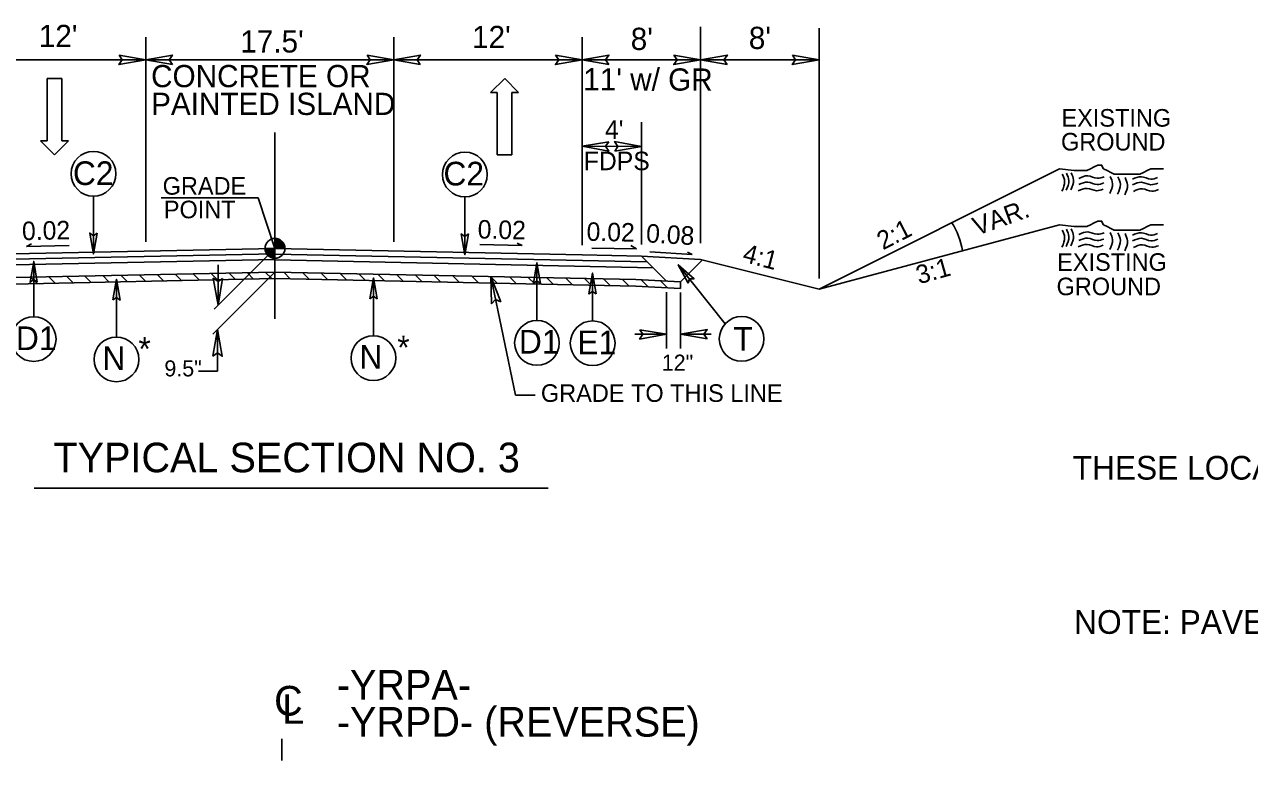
# Model space of a CAD drawing. Extents: x 573813 to 575363, y -54752 to -53123.
# Drawn here: x 574834.1 to 574928.2, y -53497.7 to -53441.2 of the extents above; entities that cross this region are included whole.
import ezdxf

# ---------------------------------------------------------------- set-up
doc = ezdxf.new("R2010")
doc.units = 0
for name, color, linetype in [('Old_Level_1', 7, 'Continuous'), ('Old_Level_11', 7, 'Continuous'), ('Old_Level_2', 7, 'Continuous'), ('Old_Level_3', 7, 'Continuous'), ('Prop Lane Arrow CELL', 7, 'Continuous'), ('Prop Pavement Schedule Description CELL', 7, 'Continuous'), ('Typical Grade Point Symbol CELL', 7, 'Continuous'), ('Typical ID Circle CELL', 7, 'Continuous'), ('Typical Terminator CELL', 7, 'Continuous'), ('Typical Text ID Circle CELL', 7, 'Continuous')]:
    doc.layers.add(name, color=color, linetype=linetype)

msp = doc.modelspace()

# ---------------------------------------------------------------- linework, layer by layer
at = {"layer": 'Old_Level_1'}
for p, q in [((574895.117, -53461.543), (574913.593, -53452.305)), ((574895.117, -53461.543), (574913.593, -53456.608)), ((574853.333, -53458.418), (574829.741, -53458.908)), ((574834.258, -53458.269), (574834.638, -53458.079)), ((574837.528, -53458.201), (574834.258, -53458.269)), ((574853.333, -53458.418), (574876.925, -53458.908)), ((574869.063, -53458.13), (574872.325, -53458.198)), ((574872.325, -53458.198), (574871.946, -53458.009)), ((574853.333, -53459.272), (574824.319, -53459.876)), ((574853.333, -53458.826), (574824.775, -53459.42)), ((574853.333, -53458.863), (574881.928, -53459.458)), ((574853.333, -53459.302), (574882.376, -53459.906)), ((574876.925, -53458.908), (574881.473, -53459.003)), ((574881.473, -53459.003), (574883.405, -53460.936)), ((574886.021, -53459.269), (574881.473, -53459.003)), ((574886.168, -53459.306), (574884.483, -53460.992)), ((574886.021, -53459.269), (574895.117, -53461.543)), ((574853.333, -53460.237), (574825.608, -53460.814)), ((574838.737, -53460.541), (574839.227, -53461.03)), ((574840.122, -53460.512), (574840.612, -53461.002)), ((574841.508, -53460.483), (574841.998, -53460.973)), ((574842.893, -53460.454), (574843.383, -53460.944)), ((574844.279, -53460.425), (574844.768, -53460.915)), ((574845.664, -53460.397), (574846.154, -53460.886)), ((574847.049, -53460.368), (574847.539, -53460.858)), ((574848.435, -53460.339), (574848.925, -53460.829)), ((574849.82, -53460.31), (574850.31, -53460.8)), ((574851.206, -53460.281), (574851.695, -53460.771)), ((574852.591, -53460.253), (574853.081, -53460.742)), ((574853.333, -53460.237), (574881.057, -53460.814)), ((574854.004, -53460.251), (574854.514, -53460.762)), ((574855.448, -53460.281), (574855.959, -53460.792)), ((574856.892, -53460.311), (574857.403, -53460.822)), ((574858.337, -53460.341), (574858.847, -53460.852)), ((574859.781, -53460.371), (574860.291, -53460.882)), ((574861.225, -53460.401), (574861.736, -53460.912)), ((574862.669, -53460.431), (574863.18, -53460.942)), ((574864.114, -53460.461), (574864.624, -53460.972)), ((574865.558, -53460.491), (574866.069, -53461.002)), ((574867.002, -53460.521), (574867.513, -53461.032)), ((574853.333, -53460.737), (574825.625, -53461.313)), ((574834.581, -53460.627), (574835.071, -53461.117)), ((574835.966, -53460.598), (574836.456, -53461.088)), ((574837.351, -53460.569), (574837.841, -53461.059)), ((574853.333, -53460.737), (574881.039, -53461.314)), ((574868.446, -53460.552), (574868.957, -53461.062)), ((574869.891, -53460.582), (574870.401, -53461.092)), ((574871.335, -53460.612), (574871.846, -53461.122)), ((574872.779, -53460.642), (574873.29, -53461.152)), ((574874.223, -53460.672), (574874.734, -53461.182)), ((574875.668, -53460.702), (574876.178, -53461.212)), ((574877.112, -53460.732), (574877.623, -53461.243)), ((574878.556, -53460.762), (574879.067, -53461.273)), ((574880, -53460.792), (574880.511, -53461.303)), ((574884.483, -53461.492), (574881.039, -53461.314)), ((574884.483, -53460.992), (574881.057, -53460.814)), ((574881.457, -53460.835), (574881.985, -53461.363)), ((574882.949, -53460.912), (574883.477, -53461.44)), ((574884.441, -53460.989), (574884.483, -53461.032)), ((574884.483, -53460.992), (574884.483, -53461.492))]:
    msp.add_line(p, q, dxfattribs=at)
for points in [[(574913.593, -53452.305), (574914.713, -53452.445), (574914.993, -53452.445), (574915.414, -53452.445), (574915.694, -53452.445), (574915.974, -53452.306), (574916.255, -53452.165), (574916.535, -53452.024), (574916.815, -53452.024), (574916.956, -53452.305), (574917.236, -53452.445), (574917.516, -53452.585), (574917.796, -53452.725), (574918.076, -53452.725), (574918.357, -53452.725), (574918.637, -53452.725), (574918.917, -53452.725), (574919.197, -53452.725), (574919.477, -53452.725), (574919.757, -53452.725), (574920.038, -53452.585), (574920.318, -53452.445), (574920.598, -53452.305), (574921.018, -53452.305), (574921.299, -53452.305), (574921.579, -53452.305)], [(574913.593, -53456.608), (574914.713, -53456.747), (574914.993, -53456.747), (574915.414, -53456.747), (574915.694, -53456.747), (574915.974, -53456.608), (574916.255, -53456.467), (574916.535, -53456.326), (574916.815, -53456.326), (574916.956, -53456.607), (574917.236, -53456.747), (574917.516, -53456.888), (574917.796, -53457.027), (574918.076, -53457.027), (574918.357, -53457.027), (574918.637, -53457.027), (574918.917, -53457.027), (574919.197, -53457.027), (574919.477, -53457.027), (574919.757, -53457.027), (574920.038, -53456.888), (574920.318, -53456.747), (574920.598, -53456.607), (574921.018, -53456.608), (574921.299, -53456.608), (574921.579, -53456.607)]]:
    msp.add_lwpolyline(points, dxfattribs=at)
at = {"layer": 'Old_Level_11'}
for p, q in [((574886.021, -53458.02), (574886.021, -53441.414)), ((574895.134, -53460.736), (574895.135, -53441.498)), ((574843.407, -53457.908), (574843.407, -53442.205)), ((574862.451, -53457.908), (574862.451, -53442.205)), ((574876.925, -53458.18), (574876.925, -53442.205)), ((574843.407, -53443.942), (574829.763, -53443.942)), ((574853.333, -53443.942), (574843.407, -53443.942)), ((574857.903, -53443.942), (574853.333, -53443.942)), ((574862.451, -53443.942), (574857.903, -53443.942)), ((574876.925, -53443.942), (574862.451, -53443.942)), ((574876.925, -53443.942), (574886.021, -53443.942)), ((574886.021, -53443.942), (574895.117, -53443.943)), ((574881.473, -53458.116), (574881.473, -53448.736)), ((574876.925, -53450.581), (574881.473, -53450.587)), ((574844.597, -53454.544), (574852.032, -53454.545)), ((574853.333, -53458.418), (574852.032, -53454.545)), ((574853.333, -53458.418), (574848.662, -53463.088)), ((574853.333, -53460.237), (574848.559, -53465.01)), ((574848.962, -53462.765), (574848.962, -53459.69)), ((574871.812, -53469.697), (574869.905, -53460.582)), ((574883.392, -53466.094), (574883.391, -53461.777)), ((574884.469, -53466.094), (574884.469, -53461.801)), ((574848.925, -53467.857), (574848.925, -53464.645)), ((574883.392, -53465.013), (574880.96, -53465.016)), ((574886.828, -53465.008), (574884.469, -53465.011)), ((574847.455, -53467.857), (574848.925, -53467.857)), ((574873.325, -53469.697), (574871.812, -53469.697)), ((574834.842, -53476.822), (574874.322, -53476.823))]:
    msp.add_line(p, q, dxfattribs=at)
for points in [[(574841.36, -53443.59), (574843.407, -53443.942), (574841.349, -53444.306), (574841.61, -53443.942)], [(574845.453, -53444.295), (574843.407, -53443.942), (574845.465, -53443.579), (574845.203, -53443.942)], [(574860.405, -53443.59), (574862.451, -53443.942), (574860.393, -53444.306), (574860.655, -53443.942)], [(574864.498, -53444.295), (574862.451, -53443.942), (574864.509, -53443.578), (574864.248, -53443.942)], [(574874.879, -53443.59), (574876.925, -53443.942), (574874.867, -53444.306), (574875.128, -53443.942)], [(574878.971, -53444.295), (574876.925, -53443.942), (574878.983, -53443.578), (574878.721, -53443.942)], [(574883.974, -53443.59), (574886.021, -53443.942), (574883.963, -53444.306), (574884.224, -53443.942)], [(574888.067, -53444.295), (574886.021, -53443.942), (574888.079, -53443.579), (574887.817, -53443.942)], [(574893.07, -53443.59), (574895.117, -53443.943), (574893.059, -53444.306), (574893.32, -53443.943)], [(574878.971, -53450.228), (574876.925, -53450.581), (574878.983, -53450.944), (574878.721, -53450.581)], [(574879.426, -53450.94), (574881.473, -53450.587), (574879.415, -53450.223), (574879.676, -53450.587)], [(574849.315, -53460.719), (574848.962, -53462.765), (574848.598, -53460.707), (574848.962, -53460.969)], [(574870.67, -53462.512), (574869.905, -53460.582), (574869.972, -53462.671), (574870.274, -53462.34)], [(574848.572, -53466.691), (574848.925, -53464.645), (574849.289, -53466.703), (574848.925, -53466.441)], [(574881.345, -53464.66), (574883.392, -53465.013), (574881.334, -53465.377), (574881.595, -53465.013)], [(574886.516, -53465.364), (574884.469, -53465.011), (574886.527, -53464.648), (574886.266, -53465.011)]]:
    msp.add_lwpolyline(points, close=True, dxfattribs=at)
msp.add_arc((574901.035, -53459.32), 5.147, 8.03481, 33.91244, dxfattribs=at)
at = {"layer": 'Old_Level_2'}
for p, q in [((574853.333, -53463.837), (574853.333, -53449.515)), ((574881.1, -53458.46), (574877.667, -53458.392)), ((574881.1, -53458.46), (574880.669, -53458.2)), ((574882.136, -53458.686), (574885.386, -53458.88)), ((574885.386, -53458.88), (574885.004, -53458.699)), ((574853.873, -53497.74), (574853.873, -53496.072))]:
    msp.add_line(p, q, dxfattribs=at)
for points in [[(574913.788, -53452.708), (574913.98, -53453.272), (574913.773, -53454.021)], [(574913.788, -53452.708), (574913.98, -53453.272), (574913.773, -53454.021)], [(574914.12, -53452.643), (574914.31, -53453.209), (574914.103, -53453.959)], [(574914.12, -53452.643), (574914.31, -53453.209), (574914.103, -53453.959)], [(574914.474, -53452.606), (574914.668, -53453.172), (574914.46, -53453.919)], [(574914.474, -53452.606), (574914.668, -53453.172), (574914.46, -53453.919)], [(574915.078, -53453.047), (574915.76, -53452.85), (574916.486, -53453.034), (574917.004, -53452.917)], [(574917.47, -53452.885), (574917.66, -53453.449), (574917.456, -53454.198)], [(574917.47, -53452.885), (574917.66, -53453.449), (574917.456, -53454.198)], [(574918.066, -53452.931), (574918.258, -53453.497), (574918.052, -53454.246)], [(574918.066, -53452.931), (574918.258, -53453.497), (574918.052, -53454.246)], [(574918.618, -53452.981), (574918.81, -53453.547), (574918.602, -53454.294)], [(574918.618, -53452.981), (574918.81, -53453.547), (574918.602, -53454.294)], [(574919.183, -53453.111), (574919.869, -53452.916), (574920.589, -53453.101), (574921.111, -53452.985)], [(574915.021, -53454.003), (574915.705, -53453.81), (574916.431, -53453.99), (574916.951, -53453.875)], [(574915.021, -53454.003), (574915.705, -53453.81), (574916.431, -53453.99), (574916.951, -53453.875)], [(574915.074, -53453.522), (574915.76, -53453.329), (574916.48, -53453.513), (574917, -53453.396)], [(574915.074, -53453.522), (574915.76, -53453.329), (574916.48, -53453.513), (574917, -53453.396)], [(574919.201, -53453.54), (574919.887, -53453.343), (574920.607, -53453.53), (574921.13, -53453.413)], [(574919.201, -53453.54), (574919.887, -53453.343), (574920.607, -53453.53), (574921.13, -53453.413)], [(574919.271, -53454.037), (574919.955, -53453.841), (574920.679, -53454.026), (574921.199, -53453.908)], [(574919.271, -53454.037), (574919.955, -53453.841), (574920.679, -53454.026), (574921.199, -53453.908)], [(574913.788, -53457.01), (574913.98, -53457.574), (574913.773, -53458.323)], [(574913.788, -53457.01), (574913.98, -53457.574), (574913.773, -53458.323)], [(574914.12, -53456.945), (574914.31, -53457.511), (574914.103, -53458.261)], [(574914.12, -53456.945), (574914.31, -53457.511), (574914.103, -53458.261)], [(574914.474, -53456.908), (574914.668, -53457.474), (574914.46, -53458.221)], [(574914.474, -53456.908), (574914.668, -53457.474), (574914.46, -53458.221)], [(574915.074, -53457.824), (574915.76, -53457.631), (574916.48, -53457.816), (574917, -53457.698)], [(574915.074, -53457.824), (574915.76, -53457.631), (574916.48, -53457.816), (574917, -53457.698)], [(574915.078, -53457.349), (574915.76, -53457.152), (574916.486, -53457.336), (574917.004, -53457.219)], [(574917.47, -53457.188), (574917.66, -53457.751), (574917.456, -53458.501)], [(574917.47, -53457.188), (574917.66, -53457.751), (574917.456, -53458.501)], [(574918.066, -53457.233), (574918.258, -53457.799), (574918.052, -53458.549)], [(574918.066, -53457.233), (574918.258, -53457.799), (574918.052, -53458.549)], [(574918.618, -53457.283), (574918.81, -53457.849), (574918.602, -53458.596)], [(574918.618, -53457.283), (574918.81, -53457.849), (574918.602, -53458.596)], [(574919.183, -53457.413), (574919.869, -53457.218), (574920.589, -53457.403), (574921.111, -53457.287)], [(574919.201, -53457.843), (574919.887, -53457.645), (574920.607, -53457.832), (574921.13, -53457.715)], [(574919.201, -53457.843), (574919.887, -53457.645), (574920.607, -53457.832), (574921.13, -53457.715)], [(574915.021, -53458.305), (574915.705, -53458.112), (574916.431, -53458.292), (574916.951, -53458.177)], [(574915.021, -53458.305), (574915.705, -53458.112), (574916.431, -53458.292), (574916.951, -53458.177)], [(574919.271, -53458.339), (574919.955, -53458.144), (574920.679, -53458.328), (574921.199, -53458.211)], [(574919.271, -53458.339), (574919.955, -53458.144), (574920.679, -53458.328), (574921.199, -53458.211)]]:
    msp.add_spline(points, degree=3, dxfattribs=at)
at = {"layer": 'Prop Lane Arrow CELL'}
for p, q in [((574835.832, -53445.38), (574835.832, -53450.155)), ((574836.958, -53445.38), (574835.832, -53445.38)), ((574836.958, -53450.155), (574836.958, -53445.38)), ((574870.981, -53445.374), (574869.89, -53446.448)), ((574872.039, -53446.448), (574870.981, -53445.374)), ((574869.89, -53446.448), (574870.402, -53446.448)), ((574870.402, -53446.448), (574870.402, -53451.223)), ((574871.527, -53451.223), (574871.527, -53446.448)), ((574871.527, -53446.448), (574872.039, -53446.448)), ((574835.832, -53450.155), (574835.321, -53450.155)), ((574835.321, -53450.155), (574836.412, -53451.23)), ((574836.412, -53451.23), (574837.47, -53450.155)), ((574837.47, -53450.155), (574836.958, -53450.155)), ((574870.402, -53451.223), (574871.527, -53451.223))]:
    msp.add_line(p, q, dxfattribs=at)
at = {"layer": 'Typical Grade Point Symbol CELL'}
for p, q in [((574853.333, -53458.418), (574853.333, -53457.654)), ((574852.569, -53458.418), (574853.333, -53458.418)), ((574853.331, -53459.181), (574853.333, -53458.418)), ((574853.333, -53458.418), (574853.331, -53459.181)), ((574854.096, -53458.418), (574853.333, -53458.418))]:
    msp.add_line(p, q, dxfattribs=at)
for points in [[(574853.34, -53457.654), (574853.34, -53457.654), (574853.34, -53458.418)], [(574853.355, -53457.654), (574853.355, -53458.418)], [(574853.37, -53457.656), (574853.37, -53458.418)], [(574853.385, -53457.656), (574853.385, -53458.418)], [(574853.401, -53457.658), (574853.401, -53458.418)], [(574853.416, -53457.659), (574853.416, -53458.418)], [(574853.431, -53457.661), (574853.431, -53458.418)], [(574853.446, -53457.663), (574853.446, -53458.418)], [(574853.462, -53457.664), (574853.462, -53458.418)], [(574853.477, -53457.668), (574853.477, -53458.418)], [(574853.492, -53457.671), (574853.492, -53458.418)], [(574853.508, -53457.675), (574853.508, -53458.418)], [(574853.523, -53457.678), (574853.523, -53458.418)], [(574853.538, -53457.683), (574853.538, -53458.418)], [(574853.553, -53457.686), (574853.553, -53458.418)], [(574853.569, -53457.691), (574853.569, -53458.418)], [(574853.584, -53457.697), (574853.584, -53458.418)], [(574853.599, -53457.702), (574853.599, -53458.418)], [(574853.614, -53457.708), (574853.614, -53458.418)], [(574853.63, -53457.715), (574853.63, -53458.418)], [(574853.645, -53457.722), (574853.645, -53458.418)], [(574852.573, -53458.418), (574852.573, -53458.501)], [(574852.588, -53458.418), (574852.588, -53458.591)], [(574852.603, -53458.418), (574852.603, -53458.645)], [(574852.619, -53458.418), (574852.619, -53458.691)], [(574852.634, -53458.418), (574852.634, -53458.726)], [(574852.649, -53458.418), (574852.649, -53458.758)], [(574852.664, -53458.418), (574852.664, -53458.787)], [(574852.68, -53458.418), (574852.68, -53458.814)], [(574852.695, -53458.418), (574852.695, -53458.838)], [(574852.71, -53458.418), (574852.71, -53458.86)], [(574852.726, -53458.418), (574852.726, -53458.881)], [(574852.741, -53458.418), (574852.741, -53458.899)], [(574852.756, -53458.418), (574852.756, -53458.918)], [(574852.771, -53458.418), (574852.771, -53458.935)], [(574852.787, -53458.418), (574852.787, -53458.952)], [(574852.802, -53458.418), (574852.802, -53458.967)], [(574852.817, -53458.418), (574852.817, -53458.981)], [(574852.832, -53458.418), (574852.832, -53458.994)], [(574852.848, -53458.418), (574852.848, -53459.008)], [(574852.863, -53458.418), (574852.863, -53459.02)], [(574852.878, -53458.418), (574852.878, -53459.032)], [(574852.893, -53458.418), (574852.893, -53459.042)], [(574852.909, -53458.418), (574852.909, -53459.052)], [(574852.924, -53458.418), (574852.924, -53459.062)], [(574852.939, -53458.418), (574852.939, -53459.072)], [(574852.954, -53458.418), (574852.954, -53459.081)], [(574852.97, -53458.418), (574852.97, -53459.089)], [(574852.985, -53458.418), (574852.985, -53459.098)], [(574853, -53458.418), (574853, -53459.104)], [(574853.016, -53458.418), (574853.016, -53459.111)], [(574853.031, -53458.418), (574853.031, -53459.118)], [(574853.046, -53458.418), (574853.046, -53459.125)], [(574853.061, -53458.418), (574853.061, -53459.132)], [(574853.077, -53458.418), (574853.077, -53459.137)], [(574853.092, -53458.418), (574853.092, -53459.142)], [(574853.107, -53458.418), (574853.107, -53459.147)], [(574853.122, -53458.418), (574853.122, -53459.15)], [(574853.138, -53458.418), (574853.138, -53459.155)], [(574853.153, -53458.418), (574853.153, -53459.159)], [(574853.168, -53458.418), (574853.168, -53459.162)], [(574853.184, -53458.418), (574853.184, -53459.166)], [(574853.199, -53458.418), (574853.199, -53459.169)], [(574853.214, -53458.418), (574853.214, -53459.171)], [(574853.229, -53458.418), (574853.229, -53459.174)], [(574853.245, -53458.418), (574853.245, -53459.176)], [(574853.26, -53458.418), (574853.26, -53459.177)], [(574853.275, -53458.418), (574853.275, -53459.179)], [(574853.29, -53458.418), (574853.29, -53459.179)], [(574853.306, -53458.418), (574853.306, -53459.181)], [(574853.321, -53458.418), (574853.321, -53459.181), (574853.321, -53459.181)], [(574853.66, -53457.729), (574853.66, -53458.418)], [(574853.675, -53457.736), (574853.675, -53458.418)], [(574853.691, -53457.744), (574853.691, -53458.418)], [(574853.706, -53457.753), (574853.706, -53458.418)], [(574853.721, -53457.761), (574853.721, -53458.418)], [(574853.736, -53457.769), (574853.736, -53458.418)], [(574853.752, -53457.78), (574853.752, -53458.418)], [(574853.767, -53457.79), (574853.767, -53458.418)], [(574853.782, -53457.802), (574853.782, -53458.418)], [(574853.798, -53457.812), (574853.798, -53458.418)], [(574853.813, -53457.824), (574853.813, -53458.418)], [(574853.828, -53457.837), (574853.828, -53458.418)], [(574853.843, -53457.851), (574853.843, -53458.418)], [(574853.859, -53457.865), (574853.859, -53458.418)], [(574853.874, -53457.88), (574853.874, -53458.418)], [(574853.889, -53457.895), (574853.889, -53458.418)], [(574853.904, -53457.912), (574853.904, -53458.418)], [(574853.92, -53457.931), (574853.92, -53458.418)], [(574853.935, -53457.949), (574853.935, -53458.418)], [(574853.95, -53457.97), (574853.95, -53458.418)], [(574853.966, -53457.992), (574853.966, -53458.418)], [(574853.981, -53458.015), (574853.981, -53458.418)], [(574853.996, -53458.041), (574853.996, -53458.418)], [(574854.011, -53458.068), (574854.011, -53458.418)], [(574854.027, -53458.1), (574854.027, -53458.418)], [(574854.042, -53458.136), (574854.042, -53458.418)], [(574854.057, -53458.178), (574854.057, -53458.418)], [(574854.072, -53458.231), (574854.072, -53458.418)], [(574854.088, -53458.309), (574854.088, -53458.418)]]:
    msp.add_lwpolyline(points, dxfattribs=at)
msp.add_circle((574853.332, -53458.417), 0.763, dxfattribs=at)
for start, end in [(359.99048, 89.99048), (179.99048, 269.99048)]:
    msp.add_arc((574853.332, -53458.417), 0.763, start, end, dxfattribs=at)
at = {"layer": 'Typical ID Circle CELL'}
for p, q in [((574839.397, -53454.408), (574839.397, -53458.846)), ((574867.918, -53454.463), (574867.918, -53458.901)), ((574834.805, -53463.663), (574834.805, -53459.418)), ((574873.455, -53463.958), (574873.455, -53459.519)), ((574877.731, -53463.985), (574877.731, -53460.32)), ((574887.913, -53464.2), (574884.3, -53459.669)), ((574841.162, -53465.224), (574841.162, -53460.785)), ((574860.896, -53465.128), (574860.896, -53460.689))]:
    msp.add_line(p, q, dxfattribs=at)
for centre in [(574839.397, -53452.69), (574867.918, -53452.745), (574834.805, -53465.381), (574873.455, -53465.675), (574877.731, -53465.703), (574889.172, -53465.369), (574841.162, -53466.941), (574860.896, -53466.845)]:
    msp.add_circle(centre, 1.718, dxfattribs=at)
at = {"layer": 'Typical Terminator CELL'}
for points in [[(574839.671, -53457.256), (574839.397, -53458.846), (574839.114, -53457.247), (574839.397, -53457.45)], [(574868.191, -53457.311), (574867.918, -53458.901), (574867.635, -53457.302), (574867.918, -53457.506)], [(574835.079, -53461.009), (574834.805, -53459.418), (574834.522, -53461.017), (574834.805, -53460.814)], [(574873.181, -53461.109), (574873.455, -53459.519), (574873.738, -53461.118), (574873.455, -53460.915)], [(574878.005, -53461.91), (574877.731, -53460.32), (574877.448, -53461.919), (574877.731, -53461.716)], [(574885.077, -53461.083), (574884.3, -53459.669), (574885.518, -53460.743), (574885.17, -53460.761)], [(574840.888, -53462.375), (574841.162, -53460.785), (574841.445, -53462.384), (574841.162, -53462.181)], [(574860.622, -53462.279), (574860.896, -53460.689), (574861.179, -53462.288), (574860.896, -53462.085)]]:
    msp.add_lwpolyline(points, close=True, dxfattribs=at)

# ---------------------------------------------------------------- texts
at = {"layer": 'Old_Level_1'}
for s, height, rotation, p in [('EXISTING', 1.3502, 359.99996, (574913.734, -53449.07)), ('GROUND', 1.3502, 359.99996, (574913.7, -53450.902)), ('FDPS', 1.4208, 359.99995, (574877.05, -53452.413)), ('VAR.', 1.4208, 19.85078, (574907.238, -53457.46)), ('0.02', 1.4212, 1.19188, (574833.921, -53457.79)), ('0.02', 1.4212, 358.80838, (574868.892, -53457.654)), ('0.08', 1.4212, 356.57937, (574881.805, -53457.948)), ('2:1', 1.4208, 27.08551, (574900.024, -53458.575)), ('4:1', 1.4208, 345.34321, (574889.167, -53459.419)), ('3:1', 1.4208, 15.63504, (574902.794, -53461.181)), ('EXISTING', 1.3498, 359.99996, (574913.404, -53460.142)), ('GROUND', 1.3498, 359.99996, (574913.359, -53462.014)), ('*', 1.819, 0, (574842.849, -53467.042)), ('*', 1.819, 0, (574862.728, -53466.935)), ('TYPICAL SECTION NO. 3', 2.27395, 359.99996, (574836.322, -53475.609)), ('THESE LOCATIONS TO BE INVESTIGATED DURING CONSTRUCTION:', 1.81916, 359.99996, (574914.597, -53476.172)), ('NOTE: PAVE TO THE FACE OF GUARDRAIL ON ALL TYPICAL SECTIONS', 1.81916, 359.99996, (574914.707, -53488.015))]:
    msp.add_text(s, height=height, rotation=rotation, dxfattribs=at).set_placement(p)
at = {"layer": 'Old_Level_11'}
for s, height, p in [("12'", 1.7055, (574835.196, -53442.958)), ("17.5'", 1.7055, (574850.671, -53443.379)), ("12'", 1.7055, (574868.469, -53443.035)), ("8'", 1.7055, (574889.724, -53443.108)), ('CONCRETE OR', 1.70546, (574843.822, -53446.04)), ('PAINTED ISLAND ', 1.70546, (574843.822, -53448.172)), ('GRADE TO THIS LINE', 1.35016, (574873.757, -53470.203))]:
    msp.add_text(s, height=height, rotation=359.99996, dxfattribs=at).set_placement(p)
at = {"layer": 'Old_Level_2'}
for s, rotation, p in [('C', 359.99996, (574853.268, -53494.287)), ('L', 359.94686, (574853.889, -53494.923))]:
    msp.add_text(s, height=2.274, rotation=rotation, dxfattribs=at).set_placement(p)
at = {"layer": 'Old_Level_3'}
for s, height, rotation, p in [("8'", 1.7055, 359.83288, (574880.653, -53443.181)), ("11' w/ GR", 1.7055, 359.83288, (574877.008, -53446.281)), ("4'", 1.4208, 359.83288, (574878.675, -53450.005)), ('GRADE', 1.3502, 359.99996, (574844.708, -53454.293)), ('POINT', 1.3502, 359.99996, (574844.799, -53456.105)), ('0.02', 1.4212, 358.85426, (574877.254, -53457.831)), ('-YRPA-', 2.2739, 0, (574858.081, -53493.065)), ('-YRPD- (REVERSE)', 2.27395, 0, (574858.081, -53495.908))]:
    msp.add_text(s, height=height, rotation=rotation, dxfattribs=at).set_placement(p)
at = {"layer": 'Prop Pavement Schedule Description CELL'}
for s, p in [('C2', (574837.822, -53453.554)), ('C2', (574866.275, -53453.587)), ('D1', (574833.442, -53466.227)), ('D1', (574872.069, -53466.493)), ('E1', (574876.56, -53466.543))]:
    msp.add_text(s, height=1.8192, rotation=360, dxfattribs=at).set_placement(p)
for s, p in [('T', (574888.54, -53466.278)), ('N', (574840.089, -53467.759)), ('N', (574859.823, -53467.663))]:
    msp.add_text(s, height=1.819, dxfattribs=at).set_placement(p)
at = {"layer": 'Typical Text ID Circle CELL'}
for s, p in [('9.5"', (574844.843, -53468.247)), ('12"', (574883.043, -53467.805))]:
    msp.add_text(s, height=1.2298, dxfattribs=at).set_placement(p)

doc.saveas('drawing.dxf')
